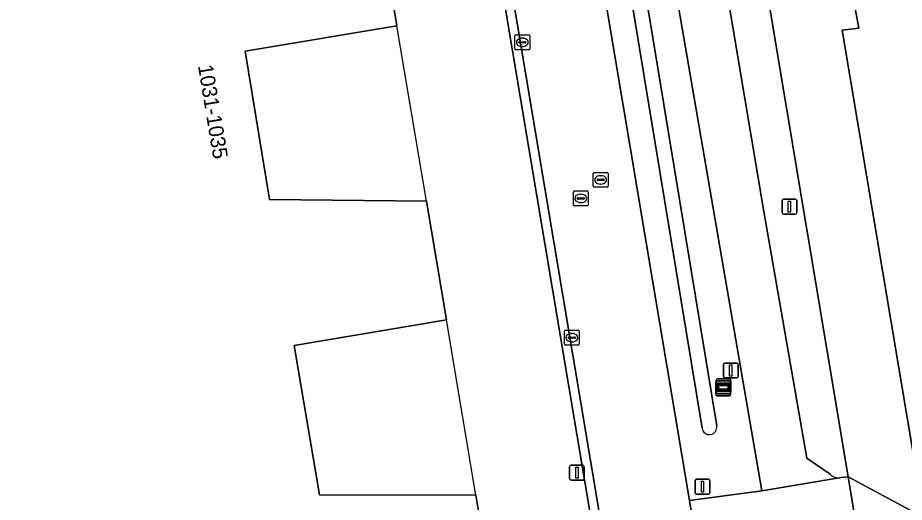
# Model space of a CAD drawing. Extents: x 154324 to 155744, y 382937 to 384188.
# Drawn here: x 155014.8 to 155074.4, y 383487.3 to 383519.8 of the extents above; entities that cross this region are included whole.
import ezdxf

# ---------------------------------------------------------------- set-up
doc = ezdxf.new("R2010")
doc.units = 0
for name, color, linetype in [('IMGEO_Berm_groen', 7, 'Continuous'), ('IMGEO_Erf', 7, 'Continuous'), ('IMGEO_Fietspad_gesloten', 7, 'Continuous'), ('IMGEO_Greppel_droge_sloot', 7, 'Continuous'), ('IMGEO_Kolk', 7, 'Continuous'), ('IMGEO_Lichtmast', 7, 'Continuous'), ('IMGEO_Pand', 7, 'Continuous'), ('IMGEO_Pand_nummerreeks', 7, 'Continuous'), ('IMGEO_Pand_overbouw', 7, 'Continuous'), ('IMGEO_Rijbaan_lokaal_gesloten', 7, 'Continuous'), ('IMGEO_Rijbaan_lokaal_open', 7, 'Continuous'), ('IMGEO_Rijbaan_regionaal_gesloten', 7, 'Continuous'), ('IMGEO_Rioolput', 7, 'Continuous'), ('IMGEO_Verkeersbordpaal', 7, 'Continuous'), ('IMGEO_Verklikker', 7, 'Continuous')]:
    doc.layers.add(name, color=color, linetype=linetype)

msp = doc.modelspace()

# ---------------------------------------------------------------- linework, layer by layer
at = {"layer": 'IMGEO_Berm_groen'}
for points in [[(155022.201, 383761.283), (155023.65, 383752.887), (155024.582, 383747.491), (155030.556, 383711.937), (155035.787, 383680.446), (155055.586, 383562.322), (155064.93, 383506.848), (155067.803, 383490.288), (155069.375, 383489.212)], [(155021.296, 383718.742), (155022.669, 383708.88), (155025.49, 383692.18), (155052.477, 383531.831), (155059.928, 383487.45), (155064.796, 383488.095), (155057.1, 383532.805), (155052.123, 383561.719), (155030.596, 383690.066)], [(155070.126, 383488.988), (155070.128, 383488.988), (155070.593, 383489.047), (155063.68, 383530.41), (155058.726, 383558.566), (155047.66, 383620.638)], [(155060.78, 383492.297), (155040.514, 383615.174)], [(155041.5, 383615.337), (155061.766, 383492.46)], [(155070.99, 383520.813), (155071.303, 383519.14), (155070.183, 383519.006), (155075.078, 383489.814), (155129.058, 383499.578), (155131.375, 383500), (155179.798, 383508.805)]]:
    msp.add_lwpolyline(points, dxfattribs=at)
for centre, radius, start, end in [((155107.254, 383550.669), 44.17, 220.30552, 239.49955), ((155061.273, 383492.379), 0.5, 189.41453, 9.35931), ((155069.982, 383489.877), 0.901, 227.60407, 279.17951)]:
    msp.add_arc(centre, radius, start, end, dxfattribs=at)
at = {"layer": 'IMGEO_Erf'}
msp.add_lwpolyline([(155058.846, 383453.397), (155045.918, 383530.449), (155024.164, 383660.104)], dxfattribs=at)
msp.add_lwpolyline([(154995.441, 383472.207), (154985.474, 383531.415), (155036.823, 383540.015), (155036.983, 383539.019), (155026.768, 383537.289), (155028.46, 383527.301), (155038.974, 383527.261), (155040.294, 383519.291), (155030.102, 383517.603), (155031.749, 383507.659), (155042.274, 383507.548), (155043.622, 383499.583), (155033.407, 383497.855), (155035.104, 383487.827), (155045.588, 383487.816), (155046.763, 383480.845)], close=True, dxfattribs=at)
at = {"layer": 'IMGEO_Fietspad_gesloten'}
for points in [[(155035.787, 383680.446), (155030.556, 383711.937), (155024.582, 383747.491), (155023.65, 383752.887), (155020.155, 383752.117), (155027.003, 383711.594), (155027.513, 383708.543), (155029.197, 383698.769), (155030.596, 383690.066), (155052.123, 383561.719), (155057.1, 383532.805), (155064.796, 383488.095), (155070.126, 383488.988)], [(155069.375, 383489.212), (155067.803, 383490.288), (155064.93, 383506.848), (155055.586, 383562.322), (155035.787, 383680.446)], [(155070.513, 383485.135), (155071.187, 383485.369), (155070.593, 383489.047), (155070.128, 383488.988), (155070.126, 383488.988), (155064.796, 383488.095), (155059.928, 383487.45), (155060.608, 383483.417), (155065.469, 383484.183), (155070.183, 383454.542), (155072.405, 383440.125)]]:
    msp.add_lwpolyline(points, dxfattribs=at)
msp.add_arc((155069.982, 383489.877), 0.901, 227.60407, 279.17951, dxfattribs=at)
at = {"layer": 'IMGEO_Greppel_droge_sloot'}
for points in [[(155040.514, 383615.174), (155060.78, 383492.297)], [(155061.766, 383492.46), (155041.5, 383615.337)]]:
    msp.add_lwpolyline(points, dxfattribs=at)
msp.add_arc((155061.273, 383492.379), 0.5, 189.41453, 9.35931, dxfattribs=at)
at = {"layer": 'IMGEO_Kolk'}
for p, q in [((155048.214, 383517.769), (155048.214, 383518.621)), ((155048.289, 383518.695), (155049.141, 383518.695)), ((155048.473, 383518.189), (155048.473, 383518.201)), ((155048.516, 383518.238), (155048.914, 383518.238)), ((155048.702, 383518.475), (155048.727, 383518.475)), ((155048.957, 383518.201), (155048.957, 383518.189)), ((155049.215, 383518.621), (155049.215, 383517.769)), ((155049.141, 383517.695), (155048.289, 383517.695)), ((155048.911, 383518.152), (155048.513, 383518.152)), ((155048.725, 383517.915), (155048.7, 383517.915)), ((155051.537, 383497.953), (155051.537, 383498.805)), ((155051.612, 383498.879), (155052.464, 383498.879)), ((155052.025, 383498.659), (155052.05, 383498.659)), ((155052.538, 383498.805), (155052.538, 383497.953)), ((155051.796, 383498.373), (155051.796, 383498.385)), ((155052.234, 383498.336), (155051.836, 383498.336)), ((155051.839, 383498.422), (155052.237, 383498.422)), ((155052.048, 383498.099), (155052.023, 383498.099)), ((155052.28, 383498.385), (155052.28, 383498.373)), ((155052.464, 383497.879), (155051.612, 383497.879))]:
    msp.add_line(p, q, dxfattribs=at)
for points in [[(155048.214, 383517.769), (155048.214, 383518.621)], [(155048.289, 383518.695), (155049.141, 383518.695)], [(155049.215, 383518.621), (155049.215, 383517.769)], [(155049.141, 383517.695), (155048.289, 383517.695)], [(155051.537, 383497.953), (155051.537, 383498.805)], [(155051.612, 383498.879), (155052.464, 383498.879)], [(155052.538, 383498.805), (155052.538, 383497.953)], [(155052.464, 383497.879), (155051.612, 383497.879)]]:
    msp.add_lwpolyline(points, dxfattribs=at)
for centre, radius, start, end in [((155048.291, 383518.619), 0.0765, 91.55205, 178.44795), ((155048.291, 383518.619), 0.0765, 91.55205, 178.44795), ((155048.513, 383518.198), 0.0403, 85.87752, 175.75265), ((155048.51, 383518.188), 0.0366, 178.93798, 274.71019), ((155048.914, 383518.195), 0.043, 264.86636, 352.45326), ((155048.918, 383518.2), 0.0386, 1.73085, 96.63898), ((155049.139, 383518.619), 0.0765, 1.55205, 88.44795), ((155049.139, 383518.619), 0.0765, 1.55205, 88.44795), ((155048.291, 383517.771), 0.0765, 181.55205, 268.44795), ((155048.291, 383517.771), 0.0765, 181.55205, 268.44795), ((155049.139, 383517.771), 0.0765, 271.55205, 358.44795), ((155049.139, 383517.771), 0.0765, 271.55205, 358.44795), ((155051.614, 383498.803), 0.0765, 91.55205, 178.44795), ((155051.614, 383498.803), 0.0765, 91.55205, 178.44795), ((155052.462, 383498.803), 0.0765, 1.55205, 88.44795), ((155052.462, 383498.803), 0.0765, 1.55205, 88.44795), ((155051.614, 383497.955), 0.0765, 181.55205, 268.44795), ((155051.614, 383497.955), 0.0765, 181.55205, 268.44795), ((155051.836, 383498.382), 0.0403, 85.87752, 175.75265), ((155051.833, 383498.372), 0.0366, 178.93798, 274.71019), ((155052.237, 383498.379), 0.043, 264.86636, 352.45326), ((155052.241, 383498.384), 0.0386, 1.73085, 96.63898), ((155052.462, 383497.955), 0.0765, 271.55205, 358.44795), ((155052.462, 383497.955), 0.0765, 271.55205, 358.44795)]:
    msp.add_arc(centre, radius, start, end, dxfattribs=at)
for centre, major_axis, ratio, start_param, end_param in [((155048.701, 383518.195), (-0.387, 0.002), 0.722429, 4.712389, 7.853982), ((155048.726, 383518.195), (-0.39, 0.002), 0.717154, 1.570796, 4.712389), ((155052.024, 383498.379), (-0.387, 0.002), 0.722429, 4.712389, 7.853982), ((155052.049, 383498.379), (-0.39, 0.002), 0.717154, 1.570796, 4.712389)]:
    msp.add_ellipse(centre, major_axis=major_axis, ratio=ratio, start_param=start_param, end_param=end_param, dxfattribs=at)
at = {"layer": 'IMGEO_Lichtmast'}
for p, q in [((155066.149, 383506.766), (155066.149, 383507.566)), ((155066.149, 383507.566), (155066.149, 383506.766)), ((155066.249, 383507.666), (155067.039, 383507.666)), ((155067.039, 383507.666), (155066.249, 383507.666)), ((155067.139, 383507.566), (155067.139, 383506.766)), ((155067.139, 383506.766), (155067.139, 383507.566)), ((155067.039, 383506.666), (155066.249, 383506.666)), ((155066.249, 383506.666), (155067.039, 383506.666)), ((155062.212, 383495.776), (155062.212, 383496.576)), ((155062.212, 383496.576), (155062.212, 383495.776)), ((155062.312, 383496.676), (155063.102, 383496.676)), ((155063.102, 383496.676), (155062.312, 383496.676)), ((155063.202, 383496.576), (155063.202, 383495.776)), ((155063.202, 383495.776), (155063.202, 383496.576)), ((155063.102, 383495.676), (155062.312, 383495.676)), ((155062.312, 383495.676), (155063.102, 383495.676)), ((155051.883, 383488.923), (155051.883, 383489.723)), ((155051.883, 383489.723), (155051.883, 383488.923)), ((155051.983, 383489.823), (155052.773, 383489.823)), ((155052.773, 383489.823), (155051.983, 383489.823)), ((155052.873, 383489.723), (155052.873, 383488.923)), ((155052.873, 383488.923), (155052.873, 383489.723)), ((155052.773, 383488.823), (155051.983, 383488.823)), ((155051.983, 383488.823), (155052.773, 383488.823))]:
    msp.add_line(p, q, dxfattribs=at)
for points in [[(155066.569, 383507.541), (155066.719, 383507.541), (155066.719, 383506.791), (155066.569, 383506.791), (155066.569, 383507.541)], [(155062.632, 383496.551), (155062.782, 383496.551), (155062.782, 383495.801), (155062.632, 383495.801), (155062.632, 383496.551)], [(155052.303, 383489.698), (155052.453, 383489.698), (155052.453, 383488.948), (155052.303, 383488.948), (155052.303, 383489.698)]]:
    msp.add_lwpolyline(points, dxfattribs=at)
for centre, start, end in [((155066.249, 383507.566), 90, 180), ((155066.249, 383507.566), 90, 180), ((155067.039, 383507.566), 0, 90), ((155067.039, 383507.566), 360, 90), ((155066.249, 383506.766), 180, 270), ((155066.249, 383506.766), 180, 270), ((155067.039, 383506.766), 270, 0), ((155067.039, 383506.766), 270, 0), ((155062.312, 383496.576), 90, 180), ((155062.312, 383496.576), 90, 180), ((155063.102, 383496.576), 0, 90), ((155063.102, 383496.576), 360, 90), ((155062.312, 383495.776), 180, 270), ((155062.312, 383495.776), 180, 270), ((155063.102, 383495.776), 270, 0), ((155063.102, 383495.776), 270, 0), ((155051.983, 383489.723), 90, 180), ((155051.983, 383489.723), 90, 180), ((155052.773, 383489.723), 0, 90), ((155052.773, 383489.723), 360, 90), ((155051.983, 383488.923), 180, 270), ((155051.983, 383488.923), 180, 270), ((155052.773, 383488.923), 270, 0), ((155052.773, 383488.923), 270, 0)]:
    msp.add_arc(centre, 0.1, start, end, dxfattribs=at)
at = {"layer": 'IMGEO_Pand'}
msp.add_lwpolyline([(155036.983, 383539.019), (155036.823, 383540.015), (154985.474, 383531.415), (154995.441, 383472.207), (155046.763, 383480.845), (155045.588, 383487.816), (155035.104, 383487.827), (155033.407, 383497.855), (155043.622, 383499.583), (155042.274, 383507.548), (155031.749, 383507.659), (155030.102, 383517.603), (155040.294, 383519.291), (155038.974, 383527.261), (155028.46, 383527.301), (155026.768, 383537.289)], close=True, dxfattribs=at)
at = {"layer": 'IMGEO_Pand_overbouw'}
for points in [[(155042.274, 383507.548), (155040.294, 383519.291), (155030.102, 383517.603), (155031.749, 383507.659)], [(155043.622, 383499.583), (155033.407, 383497.855), (155035.104, 383487.827), (155045.588, 383487.816)]]:
    msp.add_lwpolyline(points, close=True, dxfattribs=at)
at = {"layer": 'IMGEO_Rijbaan_lokaal_gesloten'}
for points in [[(155019.641, 383727.625), (155016.525, 383745.686), (155014.572, 383756.911), (155008.692, 383756.004), (155012.973, 383730.527), (155013.247, 383728.802), (155016.871, 383707.197), (155046.503, 383530.572), (155059.439, 383453.463)], [(155065.348, 383454.427), (155060.608, 383483.417), (155059.928, 383487.45), (155052.477, 383531.831)]]:
    msp.add_lwpolyline(points, dxfattribs=at)
at = {"layer": 'IMGEO_Rijbaan_lokaal_open'}
msp.add_lwpolyline([(155059.439, 383453.463), (155046.503, 383530.572), (155016.871, 383707.197), (155016.277, 383707.107), (155024.164, 383660.104), (155045.918, 383530.449), (155058.846, 383453.397), (155060.487, 383443.041), (155061.613, 383435.27), (155063.03, 383424.403), (155063.139, 383423.564), (155064.659, 383408.986), (155065.341, 383401.33), (155065.709, 383396.485), (155066.213, 383389.857), (155069.432, 383341.538), (155069.458, 383341.15), (155069.938, 383333.947), (155070.4, 383319.494), (155070.638, 383289.04), (155071.247, 383289.042), (155071.154, 383307.067)], dxfattribs=at)
at = {"layer": 'IMGEO_Rijbaan_regionaal_gesloten'}
for points in [[(155030.623, 383760.14), (155023.592, 383759.163), (155025.319, 383747.582), (155031.523, 383712.699), (155040.998, 383657.511), (155047.66, 383620.638), (155058.726, 383558.566), (155063.68, 383530.41), (155070.593, 383489.047), (155075.664, 383486.308), (155075.078, 383489.814), (155070.183, 383519.006), (155071.303, 383519.14), (155070.99, 383520.813), (155070.622, 383522.809)], [(155088.506, 383425.158), (155082.147, 383448.215), (155075.664, 383486.308), (155070.593, 383489.047), (155071.187, 383485.369), (155076.819, 383452.367), (155095.519, 383340.332), (155097.848, 383325.634), (155099.567, 383313.904), (155107.952, 383291.229), (155108.58, 383289.319), (155109.574, 383286.695)]]:
    msp.add_lwpolyline(points, dxfattribs=at)
msp.add_arc((155107.254, 383550.669), 44.17, 220.30552, 239.49955, dxfattribs=at)
at = {"layer": 'IMGEO_Rioolput'}
for p, q in [((155053.473, 383508.54), (155053.473, 383509.392)), ((155053.548, 383509.466), (155054.4, 383509.466)), ((155053.961, 383509.246), (155053.986, 383509.246)), ((155054.474, 383509.392), (155054.474, 383508.54)), ((155053.732, 383508.96), (155053.732, 383508.972)), ((155054.17, 383508.923), (155053.772, 383508.923)), ((155053.775, 383509.009), (155054.173, 383509.009)), ((155053.984, 383508.686), (155053.959, 383508.686)), ((155054.216, 383508.972), (155054.216, 383508.96)), ((155052.141, 383507.298), (155052.141, 383508.15)), ((155052.216, 383508.224), (155053.068, 383508.224)), ((155053.142, 383508.15), (155053.142, 383507.298)), ((155054.4, 383508.466), (155053.548, 383508.466)), ((155052.4, 383507.718), (155052.4, 383507.73)), ((155052.838, 383507.681), (155052.44, 383507.681)), ((155052.443, 383507.767), (155052.841, 383507.767)), ((155052.629, 383508.004), (155052.654, 383508.004)), ((155052.884, 383507.73), (155052.884, 383507.718)), ((155053.068, 383507.224), (155052.216, 383507.224)), ((155052.652, 383507.444), (155052.627, 383507.444))]:
    msp.add_line(p, q, dxfattribs=at)
for points in [[(155053.473, 383508.54), (155053.473, 383509.392)], [(155053.548, 383509.466), (155054.4, 383509.466)], [(155054.474, 383509.392), (155054.474, 383508.54)], [(155052.141, 383507.298), (155052.141, 383508.15)], [(155052.216, 383508.224), (155053.068, 383508.224)], [(155053.142, 383508.15), (155053.142, 383507.298)], [(155054.4, 383508.466), (155053.548, 383508.466)], [(155053.068, 383507.224), (155052.216, 383507.224)]]:
    msp.add_lwpolyline(points, dxfattribs=at)
for centre, radius, start, end in [((155053.55, 383509.39), 0.0765, 91.55205, 178.44795), ((155053.55, 383509.39), 0.0765, 91.55205, 178.44795), ((155054.398, 383509.39), 0.0765, 1.55205, 88.44795), ((155054.398, 383509.39), 0.0765, 1.55205, 88.44795), ((155053.772, 383508.969), 0.0403, 85.87752, 175.75265), ((155053.769, 383508.959), 0.0366, 178.93798, 274.71019), ((155054.173, 383508.966), 0.043, 264.86636, 352.45326), ((155054.177, 383508.971), 0.0386, 1.73085, 96.63898), ((155052.218, 383508.148), 0.0765, 91.55205, 178.44795), ((155052.218, 383508.148), 0.0765, 91.55205, 178.44795), ((155053.066, 383508.148), 0.0765, 1.55205, 88.44795), ((155053.066, 383508.148), 0.0765, 1.55205, 88.44795), ((155053.55, 383508.542), 0.0765, 181.55205, 268.44795), ((155053.55, 383508.542), 0.0765, 181.55205, 268.44795), ((155054.398, 383508.542), 0.0765, 271.55205, 358.44795), ((155054.398, 383508.542), 0.0765, 271.55205, 358.44795), ((155052.44, 383507.727), 0.0403, 85.87752, 175.75265), ((155052.437, 383507.717), 0.0366, 178.93798, 274.71019), ((155052.841, 383507.724), 0.043, 264.86636, 352.45326), ((155052.845, 383507.729), 0.0386, 1.73085, 96.63898), ((155052.218, 383507.3), 0.0765, 181.55205, 268.44795), ((155052.218, 383507.3), 0.0765, 181.55205, 268.44795), ((155053.066, 383507.3), 0.0765, 271.55205, 358.44795), ((155053.066, 383507.3), 0.0765, 271.55205, 358.44795)]:
    msp.add_arc(centre, radius, start, end, dxfattribs=at)
for centre, major_axis, ratio, start_param, end_param in [((155053.96, 383508.966), (-0.387, 0.002), 0.722429, 4.712389, 7.853982), ((155053.985, 383508.966), (-0.39, 0.002), 0.717154, 1.570796, 4.712389), ((155052.628, 383507.724), (-0.387, 0.002), 0.722429, 4.712389, 7.853982), ((155052.653, 383507.724), (-0.39, 0.002), 0.717154, 1.570796, 4.712389)]:
    msp.add_ellipse(centre, major_axis=major_axis, ratio=ratio, start_param=start_param, end_param=end_param, dxfattribs=at)
at = {"layer": 'IMGEO_Verkeersbordpaal'}
for p, q in [((155060.314, 383487.979), (155060.314, 383488.779)), ((155060.314, 383488.779), (155060.314, 383487.979)), ((155060.414, 383488.879), (155061.204, 383488.879)), ((155061.204, 383488.879), (155060.414, 383488.879)), ((155061.304, 383488.779), (155061.304, 383487.979)), ((155061.304, 383487.979), (155061.304, 383488.779)), ((155061.204, 383487.879), (155060.414, 383487.879)), ((155060.414, 383487.879), (155061.204, 383487.879))]:
    msp.add_line(p, q, dxfattribs=at)
msp.add_lwpolyline([(155060.734, 383488.754), (155060.884, 383488.754), (155060.884, 383488.004), (155060.734, 383488.004), (155060.734, 383488.754)], dxfattribs=at)
for centre, start, end in [((155060.414, 383488.779), 90, 180), ((155060.414, 383488.779), 90, 180), ((155061.204, 383488.779), 0, 90), ((155061.204, 383488.779), 360, 90), ((155060.414, 383487.979), 180, 270), ((155060.414, 383487.979), 180, 270), ((155061.204, 383487.979), 270, 0), ((155061.204, 383487.979), 270, 0)]:
    msp.add_arc(centre, 0.1, start, end, dxfattribs=at)
at = {"layer": 'IMGEO_Verklikker'}
for p, q in [((155061.823, 383495.621), (155062.613, 383495.621)), ((155062.613, 383495.621), (155061.823, 383495.621)), ((155061.704, 383494.574), (155061.704, 383495.374)), ((155061.704, 383495.374), (155061.704, 383494.574)), ((155061.723, 383494.721), (155061.723, 383495.521)), ((155061.723, 383495.521), (155061.723, 383494.721)), ((155061.804, 383495.474), (155062.594, 383495.474)), ((155062.594, 383495.474), (155061.804, 383495.474)), ((155062.694, 383495.374), (155062.694, 383494.574)), ((155062.694, 383494.574), (155062.694, 383495.374)), ((155062.713, 383495.521), (155062.713, 383494.721)), ((155062.713, 383494.721), (155062.713, 383495.521)), ((155062.594, 383494.474), (155061.804, 383494.474)), ((155061.804, 383494.474), (155062.594, 383494.474)), ((155062.613, 383494.621), (155061.823, 383494.621)), ((155061.823, 383494.621), (155062.613, 383494.621))]:
    msp.add_line(p, q, dxfattribs=at)
for points in [[(155061.805, 383495.206), (155062.593, 383495.206), (155062.593, 383494.742), (155061.805, 383494.742), (155061.805, 383495.206)], [(155061.824, 383495.353), (155062.612, 383495.353), (155062.612, 383494.889), (155061.824, 383494.889), (155061.824, 383495.353)], [(155061.87, 383495.141), (155061.87, 383494.807), (155062.528, 383494.807), (155062.528, 383495.141), (155061.87, 383495.141)], [(155061.889, 383495.288), (155061.889, 383494.954), (155062.547, 383494.954), (155062.547, 383495.288), (155061.889, 383495.288)]]:
    msp.add_lwpolyline(points, dxfattribs=at)
for centre, start, end in [((155061.823, 383495.521), 90, 180), ((155061.823, 383495.521), 90, 180), ((155062.613, 383495.521), 0, 90), ((155062.613, 383495.521), 360, 90), ((155061.804, 383495.374), 90, 180), ((155061.804, 383495.374), 90, 180), ((155062.594, 383495.374), 0, 90), ((155062.594, 383495.374), 360, 90), ((155061.804, 383494.574), 180, 270), ((155061.804, 383494.574), 180, 270), ((155061.823, 383494.721), 180, 270), ((155061.823, 383494.721), 180, 270), ((155062.594, 383494.574), 270, 0), ((155062.594, 383494.574), 270, 0), ((155062.613, 383494.721), 270, 0), ((155062.613, 383494.721), 270, 0)]:
    msp.add_arc(centre, 0.1, start, end, dxfattribs=at)

# ---------------------------------------------------------------- texts
at = {"layer": 'IMGEO_Pand_nummerreeks'}
msp.add_text('1031-1035', height=1, rotation=279.40288, dxfattribs=at).set_placement((155026.94, 383516.621))

doc.saveas('drawing.dxf')
